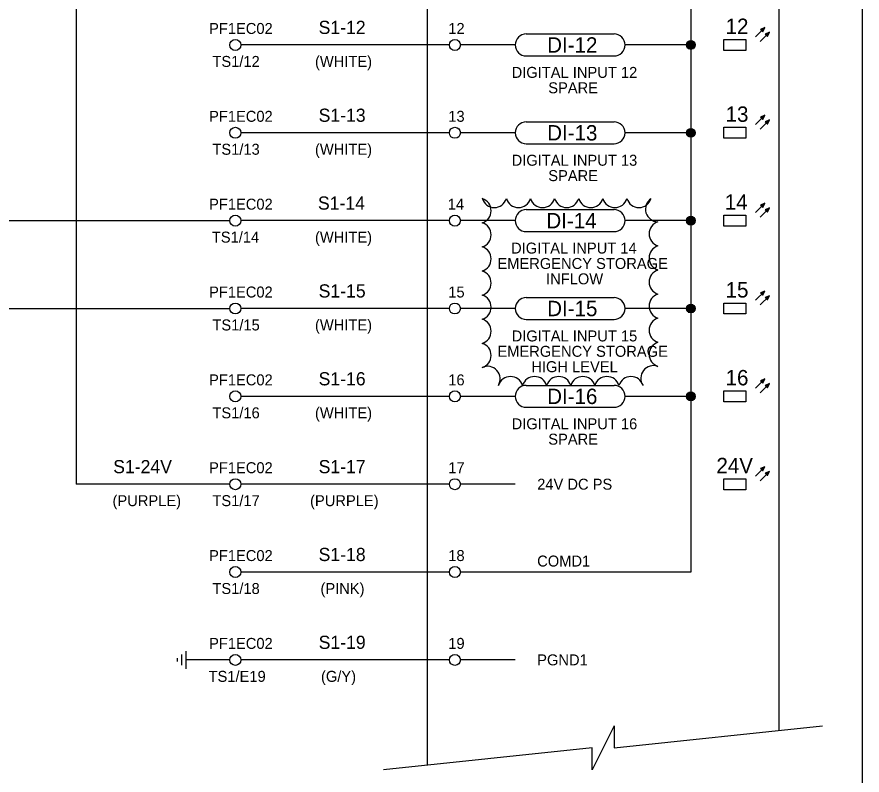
# Model space of a CAD drawing. Extents: x 0 to 841, y 0 to 594.
# Drawn here: x 636.5 to 829, y 93.8 to 266.4 of the extents above; entities that cross this region are included whole.
import ezdxf

# ---------------------------------------------------------------- set-up
doc = ezdxf.new("R2010")
doc.units = 0
for name, color, linetype in [('A1BORDER', 7, 'Continuous'), ('Level 1', 7, 'Continuous'), ('Level 10', 7, 'Continuous')]:
    doc.layers.add(name, color=color, linetype=linetype)

msp = doc.modelspace()

# ---------------------------------------------------------------- linework, layer by layer
at = {"layer": 'A1BORDER'}
msp.add_line((829, 581), (829, 15), dxfattribs=at)
at = {"layer": 'Level 1'}
for p, q in [((650, 500), (650, 160)), ((790, 480), (790, 140)), ((752.5, 262.5), (772.5, 262.5)), ((735, 260), (687.5, 260)), ((750, 260), (737.5, 260)), ((790, 260), (775, 260)), ((752.5, 257.5), (772.5, 257.5)), ((752.5, 242.5), (772.5, 242.5)), ((735, 240), (687.5, 240)), ((750, 240), (737.5, 240)), ((790, 240), (775, 240)), ((752.5, 237.5), (772.5, 237.5)), ((752.5, 222.5), (772.5, 222.5)), ((270, 220), (685, 220)), ((735, 220), (687.5, 220)), ((750, 220), (737.5, 220)), ((790, 220), (775, 220)), ((752.5, 217.5), (772.5, 217.5)), ((752.5, 202.5), (772.5, 202.5)), ((270, 200), (685, 200)), ((735, 200), (687.5, 200)), ((750, 200), (737.5, 200)), ((790, 200), (775, 200)), ((752.5, 197.5), (772.5, 197.5)), ((752.5, 182.5), (772.5, 182.5)), ((735, 180), (687.5, 180)), ((750, 180), (737.5, 180)), ((790, 180), (775, 180)), ((752.5, 177.5), (772.5, 177.5)), ((685, 160), (650, 160)), ((735, 160), (687.5, 160)), ((750, 160), (737.5, 160)), ((735, 140), (687.5, 140)), ((790, 140), (737.5, 140)), ((685, 120), (675, 120)), ((735, 120), (687.5, 120)), ((750, 120), (737.5, 120)), ((772.5, 105), (767.5, 95)), ((772.5, 105), (772.5, 100)), ((772.5, 100), (820, 105)), ((767.5, 100), (720, 95)), ((767.5, 95), (767.5, 100))]:
    msp.add_line(p, q, dxfattribs=at)
msp.add_lwpolyline([(730, 96.05), (730, 557.5), (810, 557.5), (810, 103.95)], dxfattribs=at)
for points in [[(797.5, 261.25), (802.5, 261.25), (802.5, 258.75), (797.5, 258.75)], [(797.5, 241.25), (802.5, 241.25), (802.5, 238.75), (797.5, 238.75)], [(797.5, 221.25), (802.5, 221.25), (802.5, 218.75), (797.5, 218.75)], [(797.5, 201.25), (802.5, 201.25), (802.5, 198.75), (797.5, 198.75)], [(797.5, 181.25), (802.5, 181.25), (802.5, 178.75), (797.5, 178.75)], [(797.5, 161.25), (802.5, 161.25), (802.5, 158.75), (797.5, 158.75)]]:
    msp.add_lwpolyline(points, close=True, dxfattribs=at)
for centre, radius, start, end in [((752.5, 260), 2.5, 90, 270), ((772.5, 260), 2.5, 270, 90), ((752.5, 240), 2.5, 90, 270), ((772.5, 240), 2.5, 270, 90), ((745.24, 225.87), 2.88, 197.5, 342.5), ((741.63, 222.26), 2.88, 287.5, 72.5), ((750.73, 225.87), 2.88, 197.5, 342.5), ((756.22, 225.87), 2.88, 197.5, 342.5), ((761.71, 225.87), 2.88, 197.5, 342.5), ((767.2, 225.87), 2.88, 197.5, 342.5), ((772.69, 225.87), 2.88, 197.5, 342.5), ((778.18, 225.87), 2.88, 197.5, 342.5), ((782.54, 222.62), 2.88, 124.2101, 269.2101), ((752.5, 220), 2.5, 90, 270), ((772.5, 220), 2.5, 270, 90), ((741.63, 216.77), 2.88, 287.5, 72.5), ((783.37, 217), 2.88, 107.5, 252.5), ((741.63, 211.28), 2.88, 287.5, 72.5), ((783.37, 211.51), 2.88, 107.5, 252.5), ((741.63, 205.79), 2.88, 287.5, 72.5), ((783.37, 206.02), 2.88, 107.5, 252.5), ((741.63, 200.3), 2.88, 287.5, 72.5), ((752.5, 200), 2.5, 90, 270), ((772.5, 200), 2.5, 270, 90), ((783.37, 200.54), 2.88, 107.5, 252.5), ((741.63, 194.81), 2.88, 287.5, 72.5), ((783.37, 195.05), 2.88, 107.5, 252.5), ((741.63, 189.32), 2.88, 287.5, 72.5), ((783.37, 189.56), 2.88, 107.5, 252.5), ((743.69, 183.96), 2.88, 329.5167, 114.5167), ((781.48, 184.12), 2.88, 69.3086, 214.3086), ((748.92, 181.63), 2.88, 17.5, 162.5), ((754.41, 181.63), 2.88, 17.5, 162.5), ((759.9, 181.63), 2.88, 17.5, 162.5), ((765.39, 181.63), 2.88, 17.5, 162.5), ((770.87, 181.63), 2.88, 17.5, 162.5), ((776.36, 181.63), 2.88, 17.5, 162.5), ((752.5, 180), 2.5, 90, 270), ((772.5, 180), 2.5, 270, 90)]:
    msp.add_arc(centre, radius, start, end, dxfattribs=at)
at = {"layer": 'Level 10'}
for p, q in [((804.73, 261.86), (806.86, 263.98)), ((806.29, 263.73), (806.74, 263.73)), ((806.62, 263.88), (806.81, 263.88)), ((805.79, 260.8), (807.91, 262.92)), ((805.96, 263.58), (806.67, 263.58)), ((806, 263.43), (806.61, 263.43)), ((806.14, 263.28), (806.53, 263.28)), ((806.3, 263.13), (806.47, 263.13)), ((807.02, 262.52), (807.73, 262.52)), ((807.06, 262.37), (807.66, 262.37)), ((807.21, 262.22), (807.6, 262.22)), ((807.35, 262.67), (807.8, 262.67)), ((807.36, 262.07), (807.53, 262.07)), ((807.68, 262.82), (807.87, 262.82)), ((789.01, 260.1), (790.99, 260.1)), ((789.08, 260.4), (790.92, 260.4)), ((789.29, 260.7), (790.71, 260.7)), ((790, 261), (790, 261)), ((789.02, 259.8), (790.98, 259.8)), ((789.13, 259.5), (790.87, 259.5)), ((789.4, 259.2), (790.6, 259.2)), ((804.73, 241.86), (806.86, 243.98)), ((805.79, 240.8), (807.91, 242.92)), ((805.96, 243.58), (806.67, 243.58)), ((806, 243.43), (806.61, 243.43)), ((806.14, 243.28), (806.53, 243.28)), ((806.29, 243.73), (806.74, 243.73)), ((806.3, 243.13), (806.47, 243.13)), ((806.62, 243.88), (806.81, 243.88)), ((807.35, 242.67), (807.8, 242.67)), ((807.68, 242.82), (807.87, 242.82)), ((789.29, 240.7), (790.71, 240.7)), ((790, 241), (790, 241)), ((807.02, 242.52), (807.73, 242.52)), ((807.06, 242.37), (807.66, 242.37)), ((807.21, 242.22), (807.6, 242.22)), ((807.36, 242.07), (807.53, 242.07)), ((789.01, 240.1), (790.99, 240.1)), ((789.02, 239.8), (790.98, 239.8)), ((789.08, 240.4), (790.92, 240.4)), ((789.13, 239.5), (790.87, 239.5)), ((789.4, 239.2), (790.6, 239.2)), ((804.73, 221.86), (806.86, 223.98)), ((805.96, 223.58), (806.67, 223.58)), ((806, 223.43), (806.61, 223.43)), ((806.29, 223.73), (806.74, 223.73)), ((806.62, 223.88), (806.81, 223.88)), ((805.79, 220.8), (807.91, 222.92)), ((806.14, 223.28), (806.53, 223.28)), ((806.3, 223.13), (806.47, 223.13)), ((807.02, 222.52), (807.73, 222.52)), ((807.06, 222.37), (807.66, 222.37)), ((807.21, 222.22), (807.6, 222.22)), ((807.35, 222.67), (807.8, 222.67)), ((807.36, 222.07), (807.53, 222.07)), ((807.68, 222.82), (807.87, 222.82)), ((789.01, 220.1), (790.99, 220.1)), ((789.02, 219.8), (790.98, 219.8)), ((789.08, 220.4), (790.92, 220.4)), ((789.13, 219.5), (790.87, 219.5)), ((789.29, 220.7), (790.71, 220.7)), ((790, 221), (790, 221)), ((789.4, 219.2), (790.6, 219.2)), ((804.73, 201.86), (806.86, 203.98)), ((805.79, 200.8), (807.91, 202.92)), ((805.96, 203.58), (806.67, 203.58)), ((806, 203.43), (806.61, 203.43)), ((806.14, 203.28), (806.53, 203.28)), ((806.29, 203.73), (806.74, 203.73)), ((806.3, 203.13), (806.47, 203.13)), ((806.62, 203.88), (806.81, 203.88)), ((807.02, 202.52), (807.73, 202.52)), ((807.06, 202.37), (807.66, 202.37)), ((807.21, 202.22), (807.6, 202.22)), ((807.35, 202.67), (807.8, 202.67)), ((807.68, 202.82), (807.87, 202.82)), ((789.08, 200.4), (790.92, 200.4)), ((789.29, 200.7), (790.71, 200.7)), ((790, 201), (790, 201)), ((807.36, 202.07), (807.53, 202.07)), ((789.01, 200.1), (790.99, 200.1)), ((789.02, 199.8), (790.98, 199.8)), ((789.13, 199.5), (790.87, 199.5)), ((789.4, 199.2), (790.6, 199.2)), ((804.73, 181.86), (806.86, 183.98)), ((805.79, 180.8), (807.91, 182.92)), ((805.96, 183.58), (806.67, 183.58)), ((806, 183.43), (806.61, 183.43)), ((806.14, 183.28), (806.53, 183.28)), ((806.29, 183.73), (806.74, 183.73)), ((806.3, 183.13), (806.47, 183.13)), ((806.62, 183.88), (806.81, 183.88)), ((790, 181), (790, 181)), ((807.02, 182.52), (807.73, 182.52)), ((807.06, 182.37), (807.66, 182.37)), ((807.21, 182.22), (807.6, 182.22)), ((807.35, 182.67), (807.8, 182.67)), ((807.36, 182.07), (807.53, 182.07)), ((807.68, 182.82), (807.87, 182.82)), ((789.01, 180.1), (790.99, 180.1)), ((789.02, 179.8), (790.98, 179.8)), ((789.08, 180.4), (790.92, 180.4)), ((789.13, 179.5), (790.87, 179.5)), ((789.29, 180.7), (790.71, 180.7)), ((789.4, 179.2), (790.6, 179.2)), ((804.73, 161.86), (806.86, 163.98)), ((806.29, 163.73), (806.74, 163.73)), ((806.62, 163.88), (806.81, 163.88)), ((805.79, 160.8), (807.91, 162.92)), ((805.96, 163.58), (806.67, 163.58)), ((806, 163.43), (806.61, 163.43)), ((806.14, 163.28), (806.53, 163.28)), ((806.3, 163.13), (806.47, 163.13)), ((807.02, 162.52), (807.73, 162.52)), ((807.06, 162.37), (807.66, 162.37)), ((807.21, 162.22), (807.6, 162.22)), ((807.35, 162.67), (807.8, 162.67)), ((807.36, 162.07), (807.53, 162.07)), ((807.68, 162.82), (807.87, 162.82)), ((675, 122), (675, 118)), ((673, 120.4), (673, 119.6)), ((674, 121.2), (674, 118.8))]:
    msp.add_line(p, q, dxfattribs=at)
for points in [[(806.86, 263.98), (805.88, 263.54), (806.41, 263.01)], [(807.91, 262.92), (806.94, 262.48), (807.48, 261.95)], [(806.86, 243.98), (805.88, 243.54), (806.41, 243.01)], [(807.91, 242.92), (806.94, 242.48), (807.48, 241.95)], [(806.86, 223.98), (805.88, 223.54), (806.41, 223.01)], [(807.91, 222.92), (806.94, 222.48), (807.48, 221.95)], [(806.86, 203.98), (805.88, 203.54), (806.41, 203.01)], [(807.91, 202.92), (806.94, 202.48), (807.48, 201.95)], [(806.86, 183.98), (805.88, 183.54), (806.41, 183.01)], [(807.91, 182.92), (806.94, 182.48), (807.48, 181.95)], [(806.86, 163.98), (805.88, 163.54), (806.41, 163.01)], [(807.91, 162.92), (806.94, 162.48), (807.48, 161.95)]]:
    msp.add_lwpolyline(points, close=True, dxfattribs=at)
for centre, radius in [((686.25, 260), 1.25), ((736.25, 260), 1.25), ((790, 260), 1), ((686.25, 240), 1.25), ((736.25, 240), 1.25), ((790, 240), 1), ((686.25, 220), 1.25), ((736.25, 220), 1.25), ((790, 220), 1), ((686.25, 200), 1.25), ((736.25, 200), 1.25), ((790, 200), 1), ((686.25, 180), 1.25), ((736.25, 180), 1.25), ((790, 180), 1), ((686.25, 160), 1.25), ((736.25, 160), 1.25), ((686.25, 140), 1.25), ((736.25, 140), 1.25), ((686.25, 120), 1.25), ((736.25, 120), 1.25)]:
    msp.add_circle(centre, radius, dxfattribs=at)

# ---------------------------------------------------------------- texts
at = {"layer": 'Level 1'}
for s, height, p in [('12', 3.5, (797.91, 262.5)), ('PF1EC02', 2.5, (680.27, 262.5)), ('S1-12', 3, (705.22, 262.5)), ('12', 2.5, (734.75, 262.5)), ('DI-12', 3.5, (757.27, 258.25)), ('TS1/12', 2.5, (681.03, 255)), ('(WHITE)', 2.5, (704.39, 255)), ('DIGITAL INPUT 12', 2.5, (749.18, 252.5)), ('SPARE', 2.5, (757.52, 249)), ('PF1EC02', 2.5, (680.27, 242.5)), ('S1-13', 3, (705.22, 242.5)), ('13', 2.5, (734.75, 242.5)), ('13', 3.5, (797.91, 242.5)), ('DI-13', 3.5, (757.27, 238.25)), ('TS1/13', 2.5, (681.03, 235)), ('(WHITE)', 2.5, (704.39, 235)), ('DIGITAL INPUT 13', 2.5, (749.18, 232.5)), ('SPARE', 2.5, (757.52, 229)), ('S1-14', 3, (705.07, 222.5)), ('14', 3.5, (797.73, 222.5)), ('PF1EC02', 2.5, (680.27, 222.5)), ('14', 2.5, (734.63, 222.5)), ('DI-14', 3.5, (757.09, 218.25)), ('TS1/14', 2.5, (680.9, 215)), ('(WHITE)', 2.5, (704.39, 215)), ('DIGITAL INPUT 14', 2.5, (749.05, 212.5)), ('EMERGENCY STORAGE', 2.5, (745.94, 209)), ('INFLOW', 2.5, (757.02, 205.5)), ('15', 3.5, (797.91, 202.5)), ('PF1EC02', 2.5, (680.27, 202.5)), ('S1-15', 3, (705.22, 202.5)), ('15', 2.5, (734.75, 202.5)), ('DI-15', 3.5, (757.27, 198.25)), ('TS1/15', 2.5, (681.03, 195)), ('(WHITE)', 2.5, (704.39, 195)), ('DIGITAL INPUT 15', 2.5, (749.18, 192.5)), ('EMERGENCY STORAGE', 2.5, (745.94, 189)), ('HIGH LEVEL', 2.5, (753.66, 185.5)), ('PF1EC02', 2.5, (680.27, 182.5)), ('S1-16', 3, (705.22, 182.5)), ('16', 2.5, (734.75, 182.5)), ('16', 3.5, (797.91, 182.5)), ('DI-16', 3.5, (757.27, 178.25)), ('TS1/16', 2.5, (681.03, 175)), ('(WHITE)', 2.5, (704.39, 175)), ('DIGITAL INPUT 16', 2.5, (749.18, 172.5)), ('SPARE', 2.5, (757.52, 169)), ('24V', 3.5, (795.82, 162.5)), ('S1-24V', 3, (658.43, 162.5)), ('PF1EC02', 2.5, (680.27, 162.5)), ('S1-17', 3, (705.22, 162.5)), ('17', 2.5, (734.75, 162.5)), ('24V DC PS', 2.5, (755, 158.75)), ('(PURPLE)', 2.5, (658.28, 155)), ('TS1/17', 2.5, (681.03, 155)), ('(PURPLE)', 2.5, (703.27, 155)), ('PF1EC02', 2.5, (680.27, 142.5)), ('S1-18', 3, (705.22, 142.5)), ('18', 2.5, (734.75, 142.5)), ('COMD1', 2.5, (755, 141.25)), ('TS1/18', 2.5, (681.03, 135)), ('(PINK)', 2.5, (705.64, 135)), ('S1-19', 3, (705.23, 122.5)), ('PF1EC02', 2.5, (680.27, 122.5)), ('19', 2.5, (734.75, 122.5)), ('PGND1', 2.5, (755, 118.75)), ('TS1/E19', 2.5, (680.16, 115)), ('(G/Y)', 2.5, (705.76, 115))]:
    msp.add_text(s, height=height, dxfattribs=at).set_placement(p)

doc.saveas('drawing.dxf')
